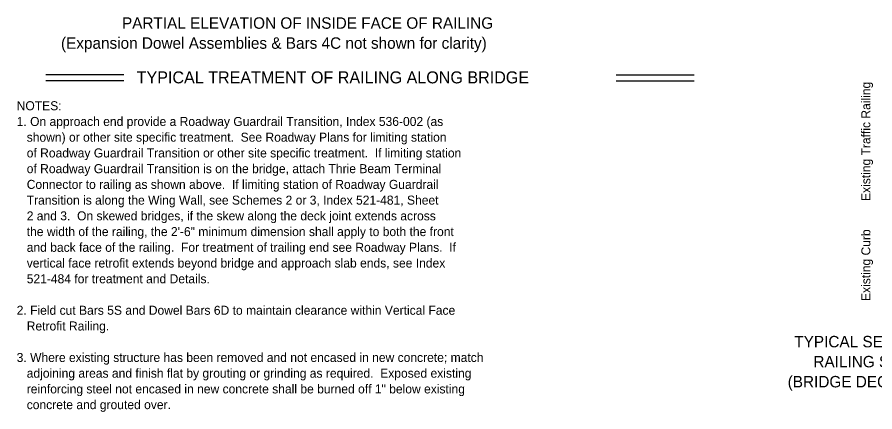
# Model space of a CAD drawing. Extents: x 0.1 to 40.1, y 0.1 to 25.4.
# Drawn here: x 0.58 to 19.74, y 0.07 to 8.9 of the extents above; entities that cross this region are included whole.
import ezdxf

# ---------------------------------------------------------------- set-up
doc = ezdxf.new("R2010")
doc.units = 0
for name, color, linetype in [('Border', 7, 'Continuous'), ('Dimension', 7, 'Continuous'), ('TextStructures', 7, 'Continuous')]:
    doc.layers.add(name, color=color, linetype=linetype)

msp = doc.modelspace()

# ---------------------------------------------------------------- linework, layer by layer
at = {"layer": 'Dimension'}
for p, q in [((2.964, 7.611), (1.22, 7.611)), ((2.964, 7.475), (1.22, 7.475)), ((13.959, 7.611), (15.703, 7.611)), ((13.959, 7.475), (15.703, 7.475))]:
    msp.add_line(p, q, dxfattribs=at)

# ---------------------------------------------------------------- texts
at = {"layer": 'Border'}
msp.add_text('TYPICAL TREATMENT OF RAILING ALONG BRIDGE', height=0.2688, dxfattribs=at).set_placement((3.248, 7.42))
at = {"layer": 'Dimension'}
for s, height, p in [('PARTIAL ELEVATION OF INSIDE FACE OF RAILING', 0.256, (2.92, 8.642)), ('(Expansion Dowel Assemblies & Bars 4C not shown for clarity)', 0.256, (1.557, 8.194)), ('NOTES:', 0.2016, (0.567, 6.819)), ('1. On approach end provide a Roadway Guardrail Transition, Index 536-002 (as ', 0.2016, (0.567, 6.467)), ('   shown) or other site specific treatment.  See Roadway Plans for limiting station ', 0.2016, (0.567, 6.115)), ('   of Roadway Guardrail Transition or other site specific treatment.  If limiting station ', 0.2016, (0.567, 5.763)), ('   of Roadway Guardrail Transition is on the bridge, attach Thrie Beam Terminal ', 0.2016, (0.567, 5.411)), ('   Connector to railing as shown above.  If limiting station of Roadway Guardrail ', 0.2016, (0.567, 5.059)), ('   Transition is along the Wing Wall, see Schemes 2 or 3, Index 521-481, Sheet ', 0.2016, (0.567, 4.707)), ('   2 and 3.  On skewed bridges, if the skew along the deck joint extends across ', 0.2016, (0.567, 4.355)), ('   the width of the railing, the 2\'-6" minimum dimension shall apply to both the front ', 0.2016, (0.567, 4.003)), ('   and back face of the railing.  For treatment of trailing end see Roadway Plans.  If', 0.2016, (0.567, 3.651)), ('   vertical face retrofit extends beyond bridge and approach slab ends, see Index ', 0.2016, (0.567, 3.299)), ('   521-484 for treatment and Details.', 0.2016, (0.567, 2.947)), ('2. Field cut Bars 5S and Dowel Bars 6D to maintain clearance within Vertical Face ', 0.2016, (0.567, 2.243)), ('   Retrofit Railing.', 0.2016, (0.567, 1.891)), ('TYPICAL SECTION THRU EXISTING TRAFFIC ', 0.256, (17.942, 1.514)), ('3. Where existing structure has been removed and not encased in new concrete; match ', 0.2016, (0.567, 1.187)), ('RAILING SHOWING LIMITS OF REMOVAL', 0.256, (18.368, 1.066)), ('   adjoining areas and finish flat by grouting or grinding as required.  Exposed existing ', 0.2016, (0.567, 0.835)), ('(BRIDGE DECK SHOWN, WING WALL SIMILAR)', 0.256, (17.794, 0.618)), ('   reinforcing steel not encased in new concrete shall be burned off 1" below existing ', 0.2016, (0.567, 0.483)), ('   concrete and grouted over.', 0.2016, (0.567, 0.131))]:
    msp.add_text(s, height=height, dxfattribs=at).set_placement(p)
at = {"layer": 'TextStructures'}
for s, p in [('Existing Traffic Railing', (19.641, 4.789)), ('Existing Curb', (19.641, 2.551))]:
    msp.add_text(s, height=0.2016, rotation=90, dxfattribs=at).set_placement(p)

doc.saveas('drawing.dxf')
